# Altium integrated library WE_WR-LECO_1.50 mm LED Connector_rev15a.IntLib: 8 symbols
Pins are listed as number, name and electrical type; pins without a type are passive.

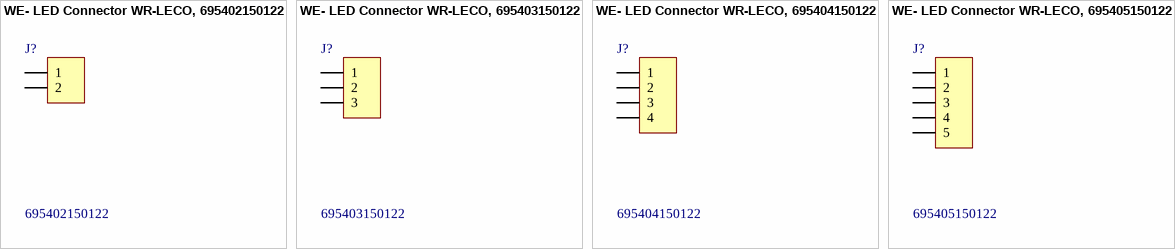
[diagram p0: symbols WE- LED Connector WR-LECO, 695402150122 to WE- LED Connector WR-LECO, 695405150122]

## WE- LED Connector WR-LECO, 695402150122
designator J?, comment 695402150122
WR-LECO 1.50mm Horizontal SMT Plug; Manufacturer: Wurth Elektronik; ComponentLink1 Description: Manufacturer; ComponentLink2 Description: Datasheet; NoPins: 2
footprint 695402150122 (SMT_Plug_Horizontal_2 pins)
pins: 1, 2

## WE- LED Connector WR-LECO, 695403150122
designator J?, comment 695403150122
WR-LECO 1.50mm Horizontal SMT Plug; Manufacturer: Wurth Elektronik; ComponentLink1 Description: Manufacturer; ComponentLink2 Description: Datasheet; NoPins: 3
footprint 695403150122 (SMT_Plug_Horizontal_3 pins)
pins: 1, 2, 3

## WE- LED Connector WR-LECO, 695404150122
designator J?, comment 695404150122
WR-LECO 1.50mm Horizontal SMT Plug; Manufacturer: Wurth Elektronik; ComponentLink1 Description: Manufacturer; ComponentLink2 Description: Datasheet; NoPins: 4
footprint 695404150122 (SMT_Plug_Horizontal_4 pins)
pins: 1, 2, 3, 4

## WE- LED Connector WR-LECO, 695405150122
designator J?, comment 695405150122
WR-LECO 1.50mm Horizontal SMT Plug; Manufacturer: Wurth Elektronik; ComponentLink1 Description: Manufacturer; ComponentLink2 Description: Datasheet; NoPins: 5
footprint 695405150122 (SMT_Plug_Horizontal_5 pins)
pins: 1, 2, 3, 4, 5


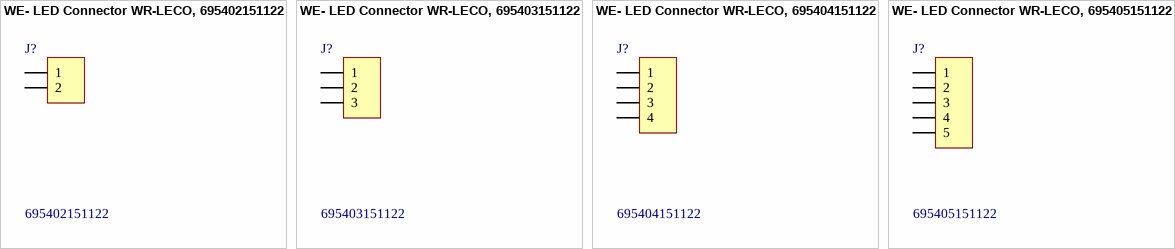
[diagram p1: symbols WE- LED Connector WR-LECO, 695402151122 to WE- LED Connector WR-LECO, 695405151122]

## WE- LED Connector WR-LECO, 695402151122
designator J?, comment 695402151122
WR-LECO 1.50mm Horizontal SMT Receptacle; Manufacturer: Wurth Elektronik; ComponentLink1 Description: Manufacturer; ComponentLink2 Description: Datasheet; NoPins: 2
footprint 695402151122 (Horizontal SMT Receptacle_ 2 pins)
pins: 1, 2

## WE- LED Connector WR-LECO, 695403151122
designator J?, comment 695403151122
WR-LECO 1.50mm Horizontal SMT Receptacle; Manufacturer: Wurth Elektronik; ComponentLink1 Description: Manufacturer; ComponentLink2 Description: Datasheet; NoPins: 3
footprint 695403151122 (Horizontal SMT Receptacle_ 3 pins)
pins: 1, 2, 3

## WE- LED Connector WR-LECO, 695404151122
designator J?, comment 695404151122
WR-LECO 1.50mm Horizontal SMT Receptacle; Manufacturer: Wurth Elektronik; ComponentLink1 Description: Manufacturer; ComponentLink2 Description: Datasheet; NoPins: 4
footprint 695404151122 (Horizontal SMT Receptacle_ 4 pins)
pins: 1, 2, 3, 4

## WE- LED Connector WR-LECO, 695405151122
designator J?, comment 695405151122
WR-LECO 1.50mm Horizontal SMT Receptacle; Manufacturer: Wurth Elektronik; ComponentLink1 Description: Manufacturer; ComponentLink2 Description: Datasheet; NoPins: 5
footprint 695405151122 (Horizontal SMT Receptacle_ 5 pins)
pins: 1, 2, 3, 4, 5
